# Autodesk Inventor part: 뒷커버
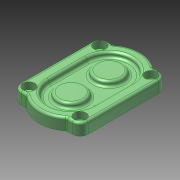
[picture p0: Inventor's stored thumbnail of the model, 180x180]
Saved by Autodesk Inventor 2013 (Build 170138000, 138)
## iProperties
Created: 2013-07
Part Number: 뒷커버
Document SubType Name: Modeling
Designer: 한국산업디자인학원
Density: 1 g/cm^3
Mass: 127.306 g
Surface Area: 321.226 cm^2
Volume: 127.306 cm^3
Material: 알루미늄 6061
Author: 한국산업디자인학원
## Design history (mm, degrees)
sketch "스케치1"
  geometry: L1 (-28.5, -82.106)-(-28.5, -34.106) reference; L2 (28.5, -34.106)-(28.5, -82.106) reference; L3 (-42.5, -103.106)-(-42.5, -13.106) reference; L4 (-26.325, -113.106)-(-32.5, -113.106) reference; L5 (32.5, -113.106)-(26.325, -113.106) reference; L6 (42.5, -13.106)-(42.5, -103.106) reference; L7 (26.325, -3.106)-(32.5, -3.106) reference; L8 (-32.5, -3.106)-(-26.325, -3.106) reference; C1 r 4.5 at (-32.5, -13.106) reference; C2 r 4.5 at (32.5, -103.106) reference; C3 r 4.5 at (-32.5, -103.106) reference; C4 r 4.5 at (32.5, -13.106) reference; A1 r 28.5 centre (0, -82.106) between (-28.5, -82.106) and (28.5, -82.106) reference; A2 r 28.5 centre (0, -34.106) between (28.5, -34.106) and (-28.5, -34.106) reference; A3 r 10 centre (-32.5, -103.106) between (-42.5, -103.106) and (-32.5, -113.106) reference; A4 r 3 centre (-26.325, -116.106) between (-24.488, -113.734) and (-26.325, -113.106) reference; A5 r 40 centre (0, -82.106) between (-24.488, -113.734) and (24.488, -113.734) reference; A6 r 3 centre (26.325, -116.106) between (26.325, -113.106) and (24.488, -113.734) reference; A7 r 10 centre (32.5, -103.106) between (32.5, -113.106) and (42.5, -103.106) reference; A8 r 10 centre (32.5, -13.106) between (42.5, -13.106) and (32.5, -3.106) reference; A9 r 3 centre (26.325, -0.106) between (24.488, -2.478) and (26.325, -3.106) reference; A10 r 40 centre (0, -34.106) between (24.488, -2.478) and (-24.488, -2.478) reference; A11 r 3 centre (-26.325, -0.106) between (-26.325, -3.106) and (-24.488, -2.478) reference; A12 r 10 centre (-32.5, -13.106) between (-32.5, -3.106) and (-42.5, -13.106) reference
extrude "돌출1" new body sketch "스케치1" distance "d0" = 15; taper "d1" = 0 deg
sketch "스케치2"
  geometry: L1 (-28.5, -34.106)-(-28.5, -82.106) reference; L2 (28.5, -82.106)-(28.5, -34.106) reference; A1 r 28.5 centre (0, -34.106) between (28.5, -34.106) and (-28.5, -34.106) reference; A2 r 28.5 centre (0, -82.106) between (-28.5, -82.106) and (28.5, -82.106) reference
extrude "돌출2" join sketch "스케치2" distance "d2" = 5; taper "d3" = 0 deg
sketch "스케치11"
  geometry: L1 (-103.106, 15)-(-13.106, 15) reference; L2 (-82.106, -5)-(-110.606, -5) reference; L3 (-82.106, -5)-(-82.106, 15); L4 (-96.106, -5)-(-96.106, 8); L5 (-96.106, 8)-(-92.106, 8); L6 (-90.106, 10)-(-82.106, 10); A1 r 2 centre (-90.106, 8) between (-90.106, 10) and (-92.106, 8); 1 further point
  constraints: 8 end point, 4 point on line, 2 parallel, 2 perpendicular, 2 point on circle, 1 centre point, 1 tangent, 1 vertical alignment
  dimensions: "d77" = 13 distance of L4.start L4.end; "d78" = 2 distance between parallel lines of L6 L5; "d79" = 28 diameter of L4 L3; "d80" = 20 diameter of L5.end L3
revolve "회전1" sketch "스케치11" stored, may be unused: angle "d81" = 90 deg
sketch "스케치8"
  geometry: L1 (28, -82.106)-(28, -34.106); L2 (-28, -82.106)-(-28, -34.106); C1 r 17.5 at (0, -82.106); C2 r 17.5 at (0, -34.106); A1 r 28 centre (0, -82.106) between (28, -82.106) and (-28, -82.106); A2 r 28 centre (0, -34.106) between (-17.161, -56.231) and (17.161, -56.231); A3 r 40 centre (0, -34.106) between (24.488, -2.478) and (-24.488, -2.478) reference; A4 r 40 centre (0, -82.106) between (-24.488, -113.734) and (24.488, -113.734) reference
  constraints: 6 point on circle, 4 centre point, 4 end point, 3 concentric, 2 equal radius, 2 parallel, 1 coincident, 1 tangent, 1 vertical
  dimensions: "d43" = 56 diameter of A1; "d44" = 35 diameter of C1
extrude "돌출5" cut sketch "스케치8" distance "d47" = 6; taper "d48" = 0 deg
fillet "모깎기1" dims "d49" = 3
fillet "모깎기2" dims "d50" = 3, "d51" = 0.3
chamfer "모따기1" distance "d52" = 1; stored, may be unused: second distance "d53" = 2, angle "d54" = 45 deg
sketch "스케치9"
  geometry: C1 r 4.5 at (-32.5, -13.106) reference; C2 r 4.5 at (32.5, -13.106) reference; C3 r 4.5 at (32.5, -103.106) reference; C4 r 4.5 at (-32.5, -103.106) reference; 1 further point
hole "구멍5" sketch "스케치9" at (-32.5, -13.106), (32.5, -13.106), (-32.5, -103.106), (32.5, -103.106) diameter "d55" = 9; stored, may be unused: countersink angle "d59" = 90 deg, drill point angle "d61" = 118 deg; dims "d56" = 6, "d57" = 15, "d58" = 8.8, "d60" = 8
node "솔리드1"
pattern_linear "직사각형 패턴1" dims "d84" = 48
node "참조10"
node "참조11"
node "참조12"
node "참조13"
node "참조14"
node "참조15"
node "참조16"
node "참조17"
node "참조18"
